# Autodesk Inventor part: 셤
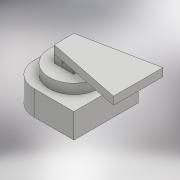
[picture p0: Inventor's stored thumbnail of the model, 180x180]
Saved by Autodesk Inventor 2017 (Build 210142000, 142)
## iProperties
Created: 2016-07
Part Number: 셤
Material: Generic
Document SubType Name: Modeling
Designer: Polytech
Density: 1 g/cm^3
Appearance: Default
Author: Polytech
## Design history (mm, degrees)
sketch "Sketch1"
  geometry: C1 r 23 at (0, 0); 1 further point
  constraints: 1 centre point, 1 coincident
  dimensions: "d0" = 46 diameter of C1
extrude "Extrusion1" new body sketch "Sketch1" distance "d1" = 18; taper "d2" = 0 deg
sketch "Sketch2"
  geometry: L1 (-11.75, 48.75)-(48.75, 48.75); L2 (48.75, 48.75)-(48.75, -48.75); L3 (48.75, -48.75)-(-11.75, -48.75); L4 (-48.75, -11.75)-(-48.75, 11.75); L5 (-48.75, 48.75)-(48.75, -48.75); L6 (48.75, 48.75)-(-48.75, -48.75); A1 r 37 centre (-11.75, 11.75) between (-11.75, 48.75) and (-48.75, 11.75); A2 r 37 centre (-11.75, -11.75) between (-48.75, -11.75) and (-11.75, -48.75); 1 further point
  constraints: 12 end point, 4 point on circle, 4 point on line, 4 tangent, 2 centre point, 2 midpoint, 2 parallel, 1 equal radius, 1 horizontal, 1 perpendicular
  dimensions: "d3" = 97.5 distance of L2.end L6.end; "d4" = 97.5 distance of L1.end L2.end; "d5" = 37 radius of A1 (derived)
extrude "Extrusion2" join sketch "Sketch2" distance "d6" = 37.5; taper "d7" = 0 deg
sketch "Sketch3"
  geometry: C1 r 37.5 at (0, 0); 1 further point
  constraints: 1 centre point, 1 coincident
  dimensions: "d8" = 75 diameter of C1
extrude "Extrusion3" join sketch "Sketch3" distance "d9" = 15; taper "d10" = 0 deg
sketch "Sketch4"
  geometry: L1 (-15, 15)-(15, 15); L2 (15, 15)-(15, -15); L3 (15, -15)-(-15, -15); L4 (-15, -15)-(-15, 15); L5 (-15, 15)-(15, -15); L6 (15, 15)-(-15, -15); 1 further point
  constraints: 12 end point, 2 midpoint, 2 parallel, 1 horizontal, 1 perpendicular
  dimensions: "d11" = 30 distance of L2.end L3.end; "d12" = 30 distance of L1.end L2.end
extrude "Extrusion4" join sketch "Sketch4" distance "d13" = 12; taper "d14" = 0 deg
sketch "Sketch5"
  geometry: L1 (-15, 6)-(15, 6); L2 (15, 6)-(15, -6); L3 (15, -6)-(-15, -6); L4 (-15, -6)-(-15, 6); L5 (-15, 6)-(15, -6); L6 (15, 6)-(-15, -6); 1 further point
  constraints: 12 end point, 2 midpoint, 2 parallel, 1 horizontal, 1 perpendicular
  dimensions: "d15" = 30 distance of L2.end L3.end; "d16" = 12 distance of L1.end L2.end
extrude "Extrusion5" cut sketch "Sketch5" distance "d17" = 12; taper "d18" = 0 deg
sketch "Sketch6"
  geometry: L1 (52.5, 0)-(-22.5, 0) reference; C1 r 3 at (15, 6); 1 further point
  constraints: 1 centre point, 1 vertical alignment
  dimensions: "d19" = 3 radius of C1; "d20" = 6 distance from line of L1 C1.centre
extrude "Extrusion6" cut sketch "Sketch6" stored distance "d21" = 12; taper "d22" = 0 deg
sketch "Sketch7"
  geometry: L1 (-15, 15)-(-15, -15); L2 (-15, -15)-(97.5, -37.5); L3 (97.5, -37.5)-(97.5, 37.5); L4 (97.5, 37.5)-(-15, 15); 4 further points
  constraints: 8 end point, 2 horizontal alignment, 2 midpoint, 1 coincident, 1 parallel, 1 vertical
  dimensions: "d23" = 97.5 distance from line of L3 point (0, 0); "d24" = 75 distance of L2.end L3.end
extrude "Extrusion7" join sketch "Sketch7" distance "d25" = 12; taper "d26" = 0 deg
sketch "Sketch8"
  geometry: C1 r 23 at (0, 0); 1 further point
  constraints: 1 centre point, 1 coincident
  dimensions: "d27" = 46 diameter of C1
extrude "Extrusion8" cut sketch "Sketch8" distance "d28" = 24.5; taper "d29" = 0 deg
body "Solid1"
